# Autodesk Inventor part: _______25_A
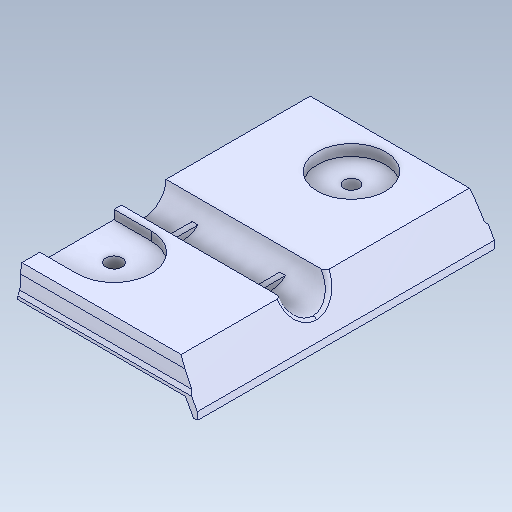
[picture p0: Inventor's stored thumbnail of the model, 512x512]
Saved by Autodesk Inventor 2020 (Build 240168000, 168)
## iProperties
Created: 2017-09
Part Number: _______25_A
Material: Générique
Document SubType Name: Modeling
Designer: bruno
Density: 1 g/cm^3
Appearance: Par défaut
Author: bruno
Sending System: SolidWorks 2016
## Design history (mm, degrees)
feature "Importée1"
node "Solide1"
